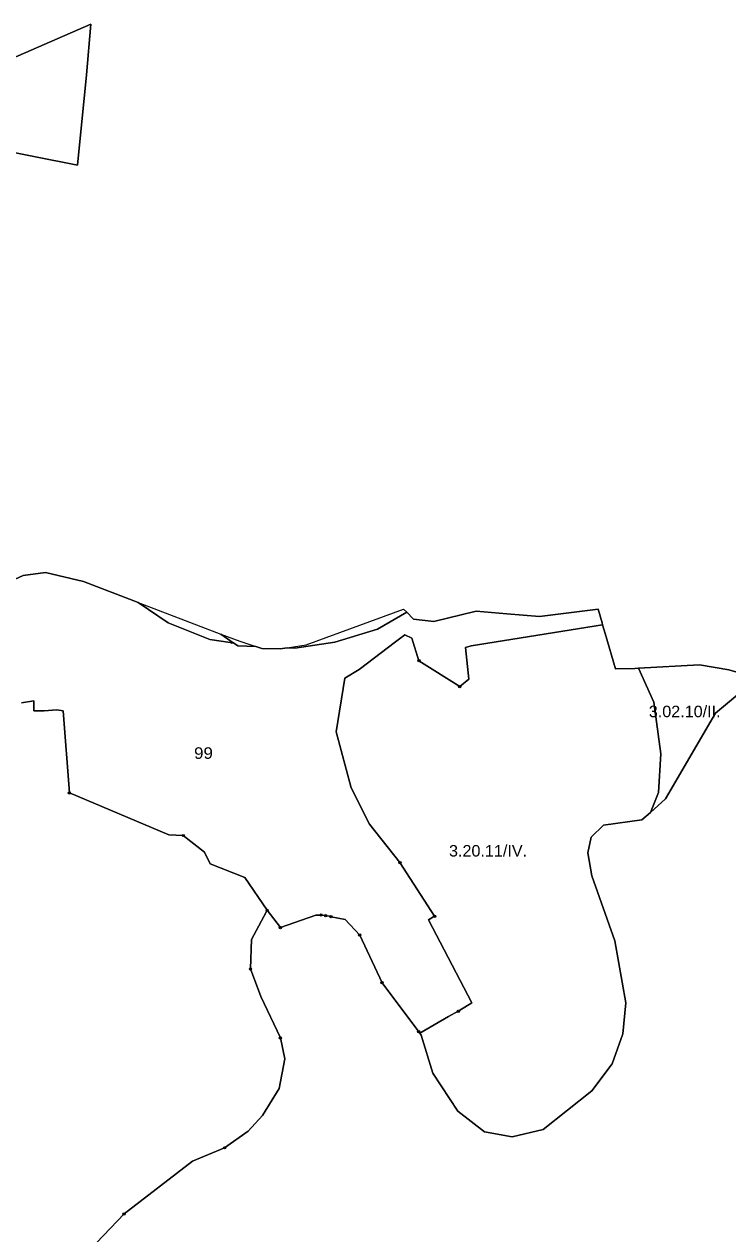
# Model space of a CAD drawing. Extents: x -650455 to -642254, y -1075222 to -1066610.
# Drawn here: x -644071 to -643459, y -1069625 to -1068574 of the extents above; entities that cross this region are included whole.
import ezdxf
from ezdxf.enums import TextEntityAlignment as Align

# ---------------------------------------------------------------- set-up
doc = ezdxf.new("R2010")
doc.units = 0
doc.header["$LTSCALE"] = 4
doc.header["$PDMODE"] = 32
doc.header["$PDSIZE"] = 2
for name, color, linetype, lineweight in [('1', 7, 'Continuous', 25), ('11', 7, 'Continuous', 13), ('12', 7, 'Continuous', 13), ('13', 7, 'Continuous', 13), ('14', 7, 'Continuous', 13), ('16', 7, 'Continuous', 13)]:
    doc.layers.add(name, color=color, linetype=linetype, lineweight=lineweight)
doc.layers.add('2', color=7, linetype='Continuous')

msp = doc.modelspace()

# ---------------------------------------------------------------- linework, layer by layer
at = {"layer": '1'}
for points in [[(-644105.749, -1068614.065), (-644012.919, -1068573.686), (-644016.645, -1068617.791), (-644024.406, -1068696.372), (-644103.575, -1068680.531)], [(-644357.5, -1069203), (-644299.717, -1069191.596), (-644268.7, -1069187.421), (-644238.23, -1069184.641), (-644221.69, -1069179.9), (-644214.53, -1069178.601), (-644201.5, -1069174.5), (-644200.5, -1069132.5), (-644200, -1069110), (-644212, -1069098.501), (-644087.5, -1069070.001), (-644085.664, -1069059.379), (-644071.881, -1069052.874), (-644052.196, -1069050.206), (-644019.287, -1069058.281), (-643971.567, -1069076.484)], [(-643971.567, -1069076.484), (-643945.5, -1069094), (-643909.5, -1069108.5), (-643891.564, -1069111.125), (-643891.55, -1069111.13), (-643890.13, -1069111.65), (-643888.83, -1069111.611), (-643888.824, -1069111.61), (-643885, -1069114), (-643869.425, -1069114.63), (-643864.053, -1069116.363), (-643848.219, -1069116.674), (-643842.005, -1069115.738), (-643835.5, -1069116.001), (-643800.5, -1069111.001), (-643763.5, -1069099.501), (-643738.043, -1069084.954), (-643732.105, -1069090.895), (-643714.408, -1069093.068), (-643677.773, -1069084.062), (-643650.919, -1069086.417), (-643622.509, -1069088.72), (-643571.628, -1069082.364), (-643568.168, -1069094.094), (-643567.686, -1069095.727), (-643682, -1069114), (-643687, -1069115.501), (-643684, -1069143.001), (-643692, -1069149.5), (-643727.5, -1069127.001), (-643733.5, -1069107.501), (-643739.66, -1069104.58), (-643747.75, -1069110.71), (-643779.31, -1069134.631), (-643792.04, -1069142.271), (-643799.5, -1069189.001), (-643786.5, -1069237.501), (-643770.5, -1069269.001), (-643744, -1069302.5), (-643713.86, -1069349.23)], [(-643536.575, -1069133.589), (-643523, -1069163.001), (-643517, -1069208.001), (-643519, -1069241.501), (-643526, -1069259), (-643533.5, -1069265.501), (-643567, -1069270.001), (-643577.5, -1069280.501), (-643580.5, -1069294.001), (-643577, -1069314.001), (-643557, -1069370.501), (-643547.5, -1069424.5), (-643550, -1069451.501), (-643559.5, -1069477.5), (-643577, -1069501), (-643619.5, -1069534.5), (-643646.5, -1069541.001), (-643670.5, -1069536.501), (-643693.5, -1069518.5), (-643715.5, -1069485.5), (-643725.5, -1069452.5), (-643726.74, -1069450.721), (-643701.88, -1069436.351), (-643693.28, -1069431.83), (-643687.502, -1069428.356), (-643681.472, -1069424.524), (-643719.17, -1069352.441), (-643713.86, -1069349.23), (-643744, -1069302.5), (-643770.5, -1069269.001), (-643786.5, -1069237.501), (-643799.5, -1069189.001), (-643792.04, -1069142.271), (-643779.31, -1069134.631), (-643747.75, -1069110.71), (-643739.66, -1069104.58), (-643733.5, -1069107.501), (-643727.5, -1069127.001), (-643692, -1069149.5), (-643684, -1069143.001)], [(-643684, -1069143.001), (-643687, -1069115.501), (-643682, -1069114), (-643567.686, -1069095.727), (-643565.388, -1069103.519), (-643556.379, -1069134.068), (-643539.614, -1069133.757), (-643536.575, -1069133.589)], [(-643817.06, -1069348.14), (-643813.705, -1069348.374), (-643812.5, -1069348), (-643808.723, -1069348.72), (-643804.83, -1069348.991), (-643803.851, -1069349.648), (-643791.5, -1069352), (-643779, -1069365.501), (-643759.5, -1069407.001), (-643727.662, -1069449.608), (-643726.74, -1069450.721), (-643725.5, -1069452.5), (-643715.5, -1069485.5), (-643693.5, -1069518.5), (-643670.5, -1069536.501), (-643646.5, -1069541.001), (-643619.5, -1069534.5), (-643577, -1069501), (-643559.5, -1069477.5), (-643550, -1069451.501), (-643547.5, -1069424.5), (-643557, -1069370.501), (-643577, -1069314.001), (-643580.5, -1069294.001), (-643577.5, -1069280.501), (-643567, -1069270.001), (-643533.5, -1069265.501), (-643526, -1069259), (-643513, -1069247), (-643469.5, -1069172.501), (-643432.983, -1069142.138)], [(-643713.86, -1069349.23), (-643719.17, -1069352.441), (-643681.472, -1069424.524), (-643687.502, -1069428.356), (-643693.28, -1069431.83), (-643701.88, -1069436.351), (-643726.74, -1069450.721), (-643727.662, -1069449.608), (-643759.5, -1069407.001), (-643779, -1069365.501), (-643791.5, -1069352), (-643803.851, -1069349.648), (-643804.83, -1069348.991), (-643808.723, -1069348.72), (-643812.5, -1069348), (-643813.705, -1069348.374), (-643817.06, -1069348.14), (-643848, -1069359.001), (-643859.5, -1069344), (-643879, -1069315.5), (-643909, -1069303.5), (-643914, -1069293.501), (-643932.5, -1069279), (-643944.89, -1069278.321), (-644031.5, -1069242), (-644037, -1069170.5), (-644042.37, -1069169.77), (-644053.451, -1069170.5), (-644062.5, -1069170.5), (-644062.5, -1069162), (-644073.229, -1069163.62)], [(-644073.229, -1069163.62), (-644062.5, -1069162), (-644062.5, -1069170.5), (-644053.451, -1069170.5), (-644042.37, -1069169.77), (-644037, -1069170.5), (-644031.5, -1069242), (-643944.89, -1069278.321), (-643932.5, -1069279), (-643914, -1069293.501), (-643909, -1069303.5), (-643879, -1069315.5), (-643859.5, -1069344)], [(-644014, -1069639.5), (-643984, -1069608), (-643924.5, -1069562), (-643896.5, -1069550.5), (-643876, -1069536.001), (-643863.5, -1069522.5), (-643849, -1069499.001), (-643844, -1069473), (-643848, -1069455.001), (-643865, -1069419.001), (-643874, -1069395.001), (-643873, -1069369.501), (-643862.5, -1069349.501), (-643859.5, -1069344), (-643848, -1069359.001), (-643817.06, -1069348.14)], [(-643859.5, -1069344), (-643862.5, -1069349.501), (-643873, -1069369.501), (-643874, -1069395.001), (-643865, -1069419.001), (-643848, -1069455.001), (-643844, -1069473), (-643849, -1069499.001), (-643863.5, -1069522.5), (-643876, -1069536.001), (-643896.5, -1069550.5), (-643924.5, -1069562), (-643984, -1069608), (-644014, -1069639.5)]]:
    msp.add_lwpolyline(points, dxfattribs=at)
for points in [[(-643888.83, -1069111.611), (-643890.13, -1069111.65), (-643891.55, -1069111.13), (-643891.564, -1069111.125), (-643909.5, -1069108.5), (-643945.5, -1069094), (-643971.567, -1069076.484), (-643899.857, -1069103.837), (-643889, -1069111.501), (-643888.836, -1069111.606)], [(-643800.5, -1069111.001), (-643835.5, -1069116.001), (-643842.005, -1069115.738), (-643825.555, -1069113.258), (-643740.798, -1069082.197), (-643738.043, -1069084.954), (-643763.5, -1069099.501)], [(-643883.302, -1069110.152), (-643869.425, -1069114.63), (-643885, -1069114), (-643888.824, -1069111.61), (-643888.83, -1069111.611), (-643888.836, -1069111.606), (-643889, -1069111.501), (-643899.857, -1069103.837)], [(-643513, -1069247), (-643526, -1069259), (-643519, -1069241.501), (-643517, -1069208.001), (-643523, -1069163.001), (-643536.575, -1069133.589), (-643483.419, -1069130.65), (-643457.961, -1069134.998), (-643432.983, -1069142.138), (-643469.5, -1069172.501)]]:
    msp.add_lwpolyline(points, close=True, dxfattribs=at)
at = {"layer": '11'}
msp.add_line((-643808.723, -1069348.72), (-643812.5, -1069348), dxfattribs=at)
for points in [[(-644103.575, -1068680.531), (-644024.406, -1068696.372), (-644016.645, -1068617.791), (-644012.919, -1068573.686), (-644105.749, -1068614.065)], [(-643432.983, -1069142.138), (-643469.5, -1069172.501), (-643513, -1069247), (-643526, -1069259), (-643533.5, -1069265.501), (-643567, -1069270.001), (-643577.5, -1069280.501), (-643580.5, -1069294.001), (-643577, -1069314.001), (-643557, -1069370.501), (-643547.5, -1069424.5), (-643550, -1069451.501), (-643559.5, -1069477.5), (-643577, -1069501), (-643619.5, -1069534.5), (-643646.5, -1069541.001), (-643670.5, -1069536.501), (-643693.5, -1069518.5), (-643715.5, -1069485.5), (-643725.5, -1069452.5), (-643726.74, -1069450.721), (-643727.662, -1069449.608)], [(-643859.5, -1069344), (-643862.5, -1069349.501), (-643873, -1069369.501), (-643874, -1069395.001)], [(-643812.5, -1069348), (-643813.705, -1069348.374), (-643817.06, -1069348.14), (-643848, -1069359.001), (-643859.5, -1069344)], [(-643779, -1069365.501), (-643791.5, -1069352), (-643803.851, -1069349.648), (-643804.83, -1069348.991), (-643808.723, -1069348.72)], [(-643727.662, -1069449.608), (-643759.5, -1069407.001), (-643779, -1069365.501)], [(-643874, -1069395.001), (-643865, -1069419.001), (-643848, -1069455.001), (-643844, -1069473), (-643849, -1069499.001), (-643863.5, -1069522.5), (-643876, -1069536.001), (-643896.5, -1069550.5), (-643924.5, -1069562), (-643984, -1069608)], [(-643984, -1069608), (-644014, -1069639.5), (-644062, -1069701), (-644056, -1069698.501), (-644086, -1069751.501), (-644087.496, -1069755.989), (-643999.727, -1069751.999), (-643995.5, -1069739.501)]]:
    msp.add_lwpolyline(points, dxfattribs=at)
for p in [(-643859.5, -1069344), (-643812.5, -1069348), (-643808.723, -1069348.72), (-643779, -1069365.501), (-643874, -1069395.001), (-643727.662, -1069449.608), (-643984, -1069608)]:
    msp.add_point(p, dxfattribs=at)
at = {"layer": '12'}
msp.add_lwpolyline([(-643519, -1069241.501), (-643526, -1069259), (-643513, -1069247), (-643469.5, -1069172.501), (-643432.983, -1069142.138), (-643457.961, -1069134.998), (-643483.419, -1069130.65), (-643536.575, -1069133.589), (-643523, -1069163.001), (-643517, -1069208.001)], close=True, dxfattribs=at)
at = {"layer": '13'}
for points in [[(-643848, -1069455.001), (-643865, -1069419.001), (-643874, -1069395.001), (-643873, -1069369.501), (-643862.5, -1069349.501), (-643859.5, -1069344), (-643879, -1069315.5), (-643909, -1069303.5), (-643914, -1069293.501), (-643932.5, -1069279), (-643944.89, -1069278.321), (-644031.5, -1069242), (-644037, -1069170.5), (-644042.37, -1069169.77), (-644053.451, -1069170.5), (-644062.5, -1069170.5), (-644062.5, -1069162), (-644073.229, -1069163.62)], [(-643896.5, -1069550.5), (-643876, -1069536.001), (-643863.5, -1069522.5), (-643849, -1069499.001), (-643844, -1069473), (-643848, -1069455.001)], [(-644212, -1069486.5), (-644184.5, -1069493.5), (-644171, -1069502.5), (-644155, -1069523), (-644129, -1069578.5), (-644120, -1069614.5), (-644121, -1069656), (-644126, -1069675.5), (-644140, -1069691.001), (-644156, -1069689), (-644140, -1069712), (-644126, -1069716.5), (-644097.5, -1069715.001), (-644062, -1069701), (-644014, -1069639.5), (-643984, -1069608)], [(-643984, -1069608), (-643924.5, -1069562), (-643896.5, -1069550.5)]]:
    msp.add_lwpolyline(points, dxfattribs=at)
for p in [(-643848, -1069455.001), (-643896.5, -1069550.5), (-643984, -1069608)]:
    msp.add_point(p, dxfattribs=at)
at = {"layer": '14'}
msp.add_line((-643744, -1069302.5), (-643713.86, -1069349.23), dxfattribs=at)
for points in [[(-643727.5, -1069127.001), (-643733.5, -1069107.501), (-643739.66, -1069104.58), (-643747.75, -1069110.71), (-643779.31, -1069134.631), (-643792.04, -1069142.271), (-643799.5, -1069189.001), (-643786.5, -1069237.501), (-643770.5, -1069269.001), (-643744, -1069302.5)], [(-643681.472, -1069424.524), (-643687.502, -1069428.356), (-643693.28, -1069431.83), (-643701.88, -1069436.351), (-643726.74, -1069450.721), (-643725.5, -1069452.5), (-643715.5, -1069485.5), (-643693.5, -1069518.5), (-643670.5, -1069536.501), (-643646.5, -1069541.001), (-643619.5, -1069534.5), (-643577, -1069501), (-643559.5, -1069477.5), (-643550, -1069451.501), (-643547.5, -1069424.5), (-643557, -1069370.501), (-643577, -1069314.001), (-643580.5, -1069294.001), (-643577.5, -1069280.501), (-643567, -1069270.001), (-643533.5, -1069265.501), (-643526, -1069259), (-643519, -1069241.501), (-643517, -1069208.001), (-643523, -1069163.001), (-643536.575, -1069133.589), (-643539.614, -1069133.757), (-643556.379, -1069134.068), (-643565.388, -1069103.519), (-643567.686, -1069095.727), (-643682, -1069114), (-643687, -1069115.501), (-643684, -1069143.001), (-643692, -1069149.5), (-643727.5, -1069127.001)], [(-643713.86, -1069349.23), (-643719.17, -1069352.441), (-643681.472, -1069424.524)]]:
    msp.add_lwpolyline(points, dxfattribs=at)
for p in [(-643727.5, -1069127.001), (-643744, -1069302.5), (-643713.86, -1069349.23)]:
    msp.add_point(p, dxfattribs=at)
at = {"layer": '16'}
for p, q in [((-644031.5, -1069242), (-643944.89, -1069278.321)), ((-643944.89, -1069278.321), (-643932.5, -1069279))]:
    msp.add_line(p, q, dxfattribs=at)
for points in [[(-643888.83, -1069111.611), (-643890.13, -1069111.65), (-643891.55, -1069111.13), (-643891.564, -1069111.125), (-643909.5, -1069108.5), (-643945.5, -1069094), (-643971.567, -1069076.484), (-644019.287, -1069058.281), (-644052.196, -1069050.206), (-644071.881, -1069052.874), (-644085.664, -1069059.379), (-644087.5, -1069070.001), (-644212, -1069098.501), (-644200, -1069110), (-644200.5, -1069132.5), (-644201.5, -1069174.5), (-644214.53, -1069178.601), (-644221.69, -1069179.9), (-644238.23, -1069184.641)], [(-643692, -1069149.5), (-643684, -1069143.001), (-643687, -1069115.501), (-643682, -1069114), (-643567.686, -1069095.727), (-643568.168, -1069094.094), (-643571.628, -1069082.364), (-643622.509, -1069088.72), (-643650.919, -1069086.417), (-643677.773, -1069084.062), (-643714.408, -1069093.068), (-643732.105, -1069090.895), (-643738.043, -1069084.954), (-643763.5, -1069099.501), (-643800.5, -1069111.001), (-643835.5, -1069116.001), (-643842.005, -1069115.738), (-643848.219, -1069116.674), (-643864.053, -1069116.363), (-643869.425, -1069114.63), (-643885, -1069114), (-643888.824, -1069111.61)], [(-643693.28, -1069431.83), (-643687.502, -1069428.356), (-643681.472, -1069424.524), (-643719.17, -1069352.441), (-643713.86, -1069349.23), (-643744, -1069302.5), (-643770.5, -1069269.001), (-643786.5, -1069237.501), (-643799.5, -1069189.001), (-643792.04, -1069142.271), (-643779.31, -1069134.631), (-643747.75, -1069110.71), (-643739.66, -1069104.58), (-643733.5, -1069107.501), (-643727.5, -1069127.001), (-643692, -1069149.5)], [(-644073.229, -1069163.62), (-644062.5, -1069162), (-644062.5, -1069170.5), (-644053.451, -1069170.5), (-644042.37, -1069169.77), (-644037, -1069170.5), (-644031.5, -1069242)], [(-643932.5, -1069279), (-643914, -1069293.501), (-643909, -1069303.5), (-643879, -1069315.5), (-643859.5, -1069344), (-643848, -1069359.001)], [(-643848, -1069359.001), (-643817.06, -1069348.14), (-643813.705, -1069348.374), (-643812.5, -1069348), (-643808.723, -1069348.72), (-643804.83, -1069348.991), (-643803.851, -1069349.648)], [(-643803.851, -1069349.648), (-643791.5, -1069352), (-643779, -1069365.501), (-643759.5, -1069407.001)], [(-643759.5, -1069407.001), (-643727.662, -1069449.608), (-643726.74, -1069450.721), (-643701.88, -1069436.351), (-643693.28, -1069431.83)]]:
    msp.add_lwpolyline(points, dxfattribs=at)
for p in [(-643692, -1069149.5), (-644031.5, -1069242), (-643932.5, -1069279), (-643803.851, -1069349.648), (-643848, -1069359.001), (-643759.5, -1069407.001), (-643693.28, -1069431.83)]:
    msp.add_point(p, dxfattribs=at)

# ---------------------------------------------------------------- texts
at = {"layer": '2'}
for s, width, p in [('3.02.10/II.', 1.05, (-643496.256, -1069176.155)), ('99', 1.1, (-643914.889, -1069212.32)), ('3.20.11/IV.', 1.05, (-643667.326, -1069297.283))]:
    msp.add_text(s, height=10, dxfattribs=dict(at, width=width)).set_placement(p, align=Align.CENTER)

doc.saveas('drawing.dxf')
